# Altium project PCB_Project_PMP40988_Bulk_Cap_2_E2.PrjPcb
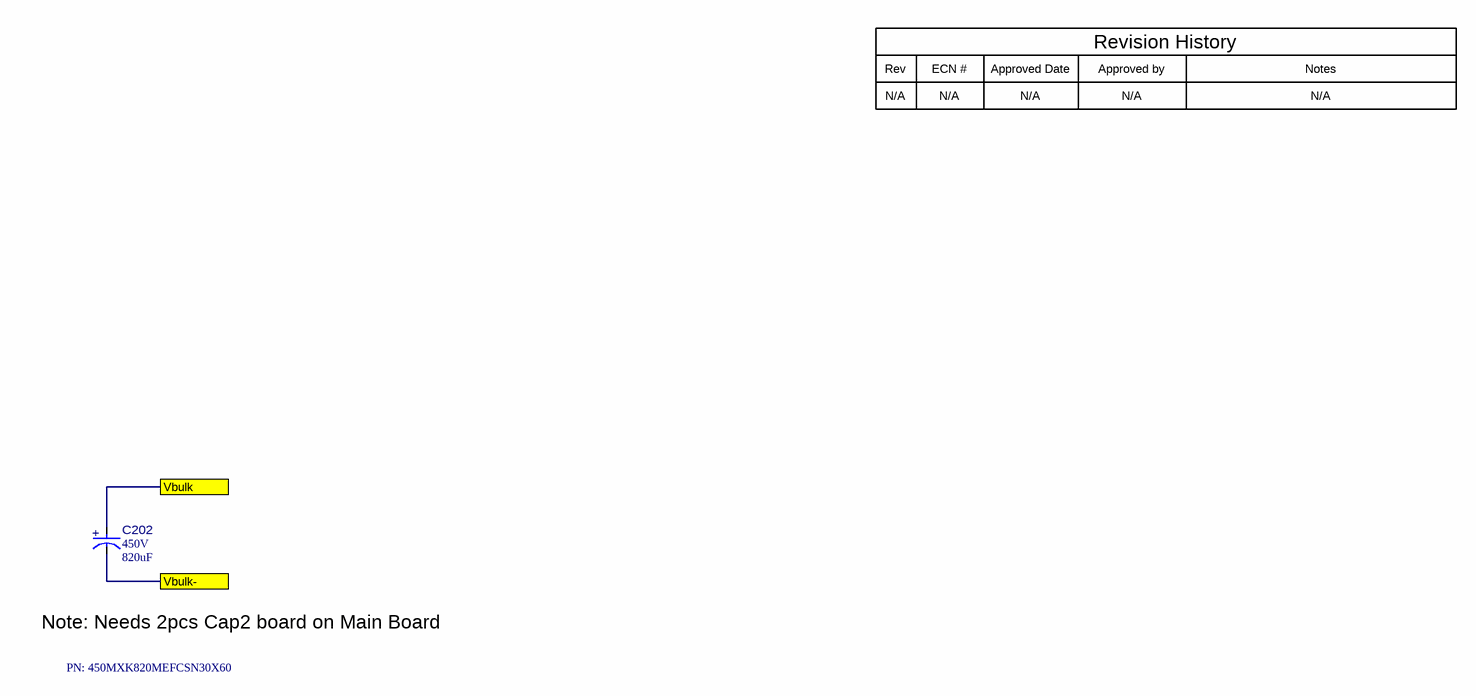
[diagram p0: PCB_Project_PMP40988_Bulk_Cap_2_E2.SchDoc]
CopyrightYear: 2022; PCB_Layout: Brent McDonald; PCB_Rev: E2; PRJ_Customer: Public Release; PRJ_Engineer: Brent McDonald; PRJ_Number: PMP40988_Bulk Cap2; PRJ_Title: PMP40988 Bulk Cap2; SCH_Rev: E2; TechSupport: http://www.ti.com/support; TID: N/A
1 sheet, 1 parts. Net scope: flat (ports and power ports of the same name join across sheets).
Board file: PCB_Project_PMP40988_Bulk_Cap_2_E2.PcbDoc

## Sheet PCB_Project_PMP40988_Bulk_Cap_2_E2.SchDoc
size 431 x 279 mm; Date: Not shown in title block; ApprovedBy: Not shown in title block; CheckedBy: Not shown in title block; Author: Not shown in title block; CompanyName: Not shown in title block; DrawnBy: San Chen; Engineer: Not shown in title block; Organization: Not shown in title block; Address1: Not shown in title block; Address2: Not shown in title block; Address3: Not shown in title block; Address4: Not shown in title block; DocumentNumber: 1; Revision: Use project parameter SCH_Rev; SheetNumber: 1; SheetTotal: 1; PageSetup: Record=PageOptions¦CenterHorizontal=True¦CenterVertical=True¦PrintScale=1.00¦XCorrection=1.00¦YCorrection=1.00¦PrintKind=0¦BorderSize=5000000¦LeftOffset=0¦BottomOffset=0¦Orientation=2¦PaperLength=1000¦PaperWidth=1000¦Scale=100¦PaperSource=15¦PrintQuality=600¦MediaType=1¦DitherType=10¦PaperKind=Letter¦PrintScaleMode=1

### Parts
C202  VDC_V: 450V  ValueDisplayed: 820uF  [FP-450MXK820MEFCFA30X60_RADIAL-MFG]  (hidden comment: 450MXK820MEFCSN30X60)

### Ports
Vbulk, Vbulk-

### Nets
Vbulk: C202.2(ANODE) ; port Vbulk
Vbulk-: C202.1(CATHODE) ; port Vbulk-

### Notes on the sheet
- Rev
- N/A
- ECN #
- Approved Date
- Approved by
- Revision History
- Notes
- Note: Needs 2pcs Cap2 board on Main Board
- PN: 450MXK820MEFCSN30X60

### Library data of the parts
C202 = CMP-0097399-1: Cap Aluminum 820uF 450V 20% Snap-In Aluminum Cylindrical Can 2.77A 3000 hr 105°C Ammo Pack; Part Number: 450MXK820MEFCFA30X60; Manufacturer: Rubycon; AEC Qualified: No; SizeZ_mm: 62mm; Cap_F: 820µF; Value: 820µF; Leakage Current: 1822.36uA; Life: 3000Hours

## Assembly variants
001: not fitted FID1 FID2 FID3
